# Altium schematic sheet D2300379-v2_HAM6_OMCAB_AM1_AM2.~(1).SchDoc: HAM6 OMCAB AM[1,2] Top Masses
size C; Engineer: L. Sanchez; Organization: LIGO Laboratory; Address1: California Institute of Technology; Address2: Massachusetts Institute of Technology; DocumentNumber: D2300379; Revision: v2; SheetNumber: 5; SheetTotal: 9
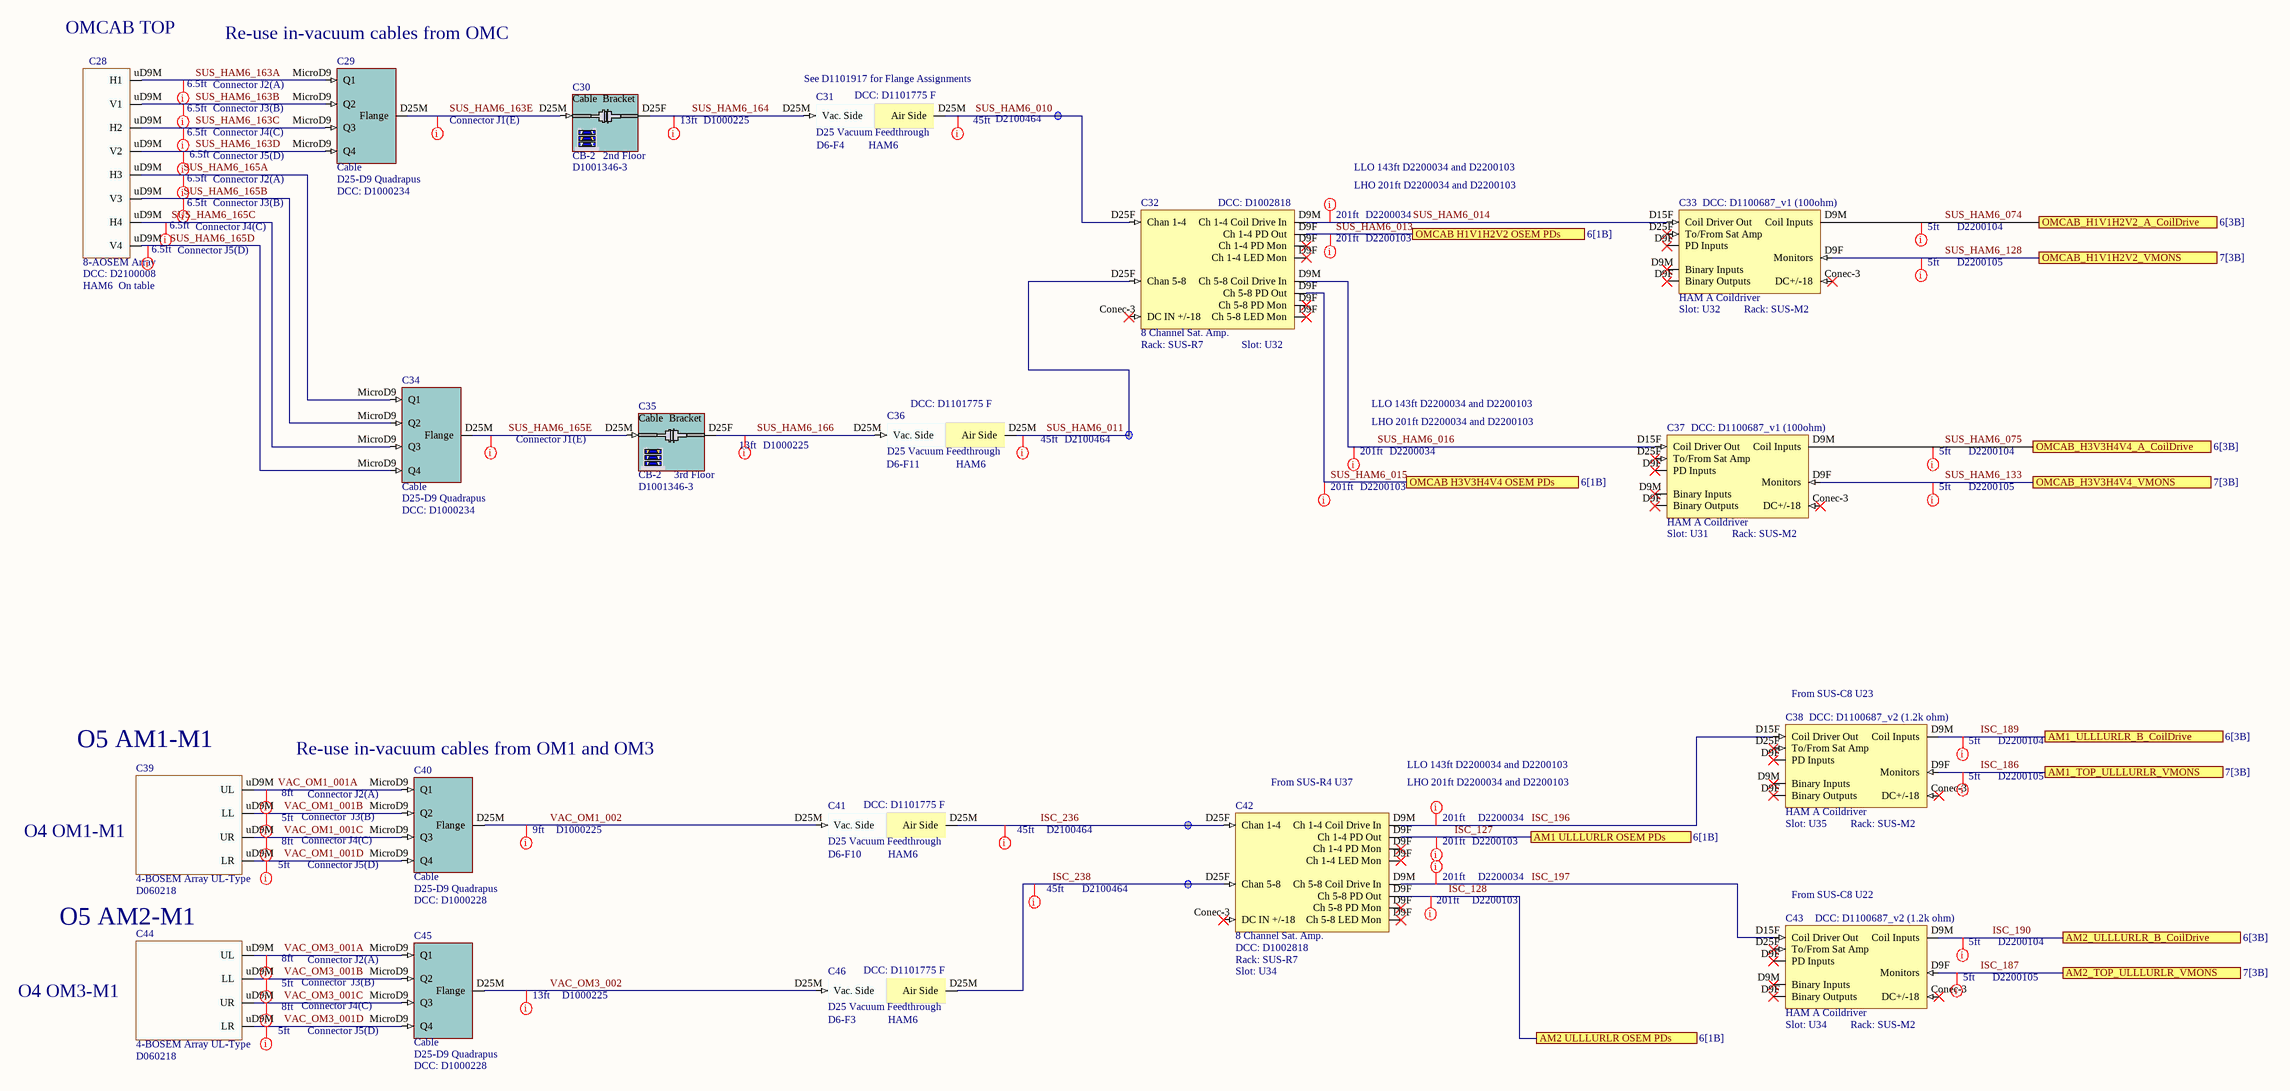
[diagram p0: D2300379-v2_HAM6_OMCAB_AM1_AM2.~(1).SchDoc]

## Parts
C28  8-AOSEM Array  DCC: D2100008  Rack: HAM6  Slot: On table
C29  Cable  value D25-D9 Quadrapus  DCC: D1000234
C30  Rack: CB-2  DCC: D1001346-3  Slot: 2nd Floor  (hidden comment: D1001346-3 2nd Cable Bracket)
C31  D25 Vacuum Feedthrough  DCC: D1101775 F  Feedthrough: D6-F4  Chamber: HAM6
C32  8 Channel Sat. Amp.  DCC: D1002818  Rack: SUS-R7  Slot: U32
C33  HAM A Coildriver  DCC: D1100687_v1 (100ohm)  Rack: SUS-M2  Slot: U32
C34  Cable  value D25-D9 Quadrapus  DCC: D1000234
C35  Rack: CB-2  DCC: D1001346-3  Slot: 3rd Floor  (hidden comment: D1001346-3 3rd Cable Bracket)
C36  D25 Vacuum Feedthrough  DCC: D1101775 F  Feedthrough: D6-F11  Chamber: HAM6
C37  HAM A Coildriver  DCC: D1100687_v1 (100ohm)  Rack: SUS-M2  Slot: U31
C38  HAM A Coildriver  DCC: D1100687_v2 (1.2k ohm)  Rack: SUS-M2  Slot: U35
C39  4-BOSEM Array UL-Type  DCC: D060218
C40  Cable  value D25-D9 Quadrapus  DCC: D1000228
C41  D25 Vacuum Feedthrough  DCC: D1101775 F  Feedthrough: D6-F10  Chamber: HAM6
C42  8 Channel Sat. Amp.  DCC: D1002818  Rack: SUS-R7  Slot: U34
C43  HAM A Coildriver  DCC: D1100687_v2 (1.2k ohm)  Rack: SUS-M2  Slot: U34
C44  4-BOSEM Array UL-Type  DCC: D060218
C45  Cable  value D25-D9 Quadrapus  DCC: D1000228
C46  D25 Vacuum Feedthrough  DCC: D1101775 F  Feedthrough: D6-F3  Chamber: HAM6

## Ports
AM1 ULLLURLR OSEM PDs (see 6[1B]), AM1_TOP_ULLLURLR_VMONS (see 7[3B]), AM1_ULLLURLR_B_CoilDrive (see 6[3B]), AM2 ULLLURLR OSEM PDs (see 6[1B]), AM2_TOP_ULLLURLR_VMONS (see 7[3B]), AM2_ULLLURLR_B_CoilDrive (see 6[3B]), OMCAB H1V1H2V2 OSEM PDs (see 6[1B]), OMCAB H3V3H4V4 OSEM PDs (see 6[1B]), OMCAB_H1V1H2V2_A_CoilDrive (see 6[3B]), OMCAB_H1V1H2V2_VMONS (see 7[3B]), OMCAB_H3V3H4V4_A_CoilDrive (see 6[3B]), OMCAB_H3V3H4V4_VMONS (see 7[3B])

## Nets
ISC_127: C42.D9F(Ch_1-4_PD_Out) ; port AM1 ULLLURLR OSEM PDs
ISC_128: C42.D9F(Ch_5-8_PD_Out) ; port AM2 ULLLURLR OSEM PDs
ISC_186: C38.D9F(PD_Inputs) ; port AM1_TOP_ULLLURLR_VMONS
ISC_187: C43.D9F(PD_Inputs) ; port AM2_TOP_ULLLURLR_VMONS
ISC_189: C38.D9M(Coil_Inputs) ; port AM1_ULLLURLR_B_CoilDrive
ISC_190: C43.D9M(Coil_Inputs) ; port AM2_ULLLURLR_B_CoilDrive
ISC_196: C38.D15F(Coil_Driver_Out) C42.D9M(Ch_1-4_Coil_Drive_In)
ISC_197: C42.D9M(Ch_5-8_Coil_Drive_In) C43.D15F(Coil_Driver_Out)
ISC_236: C41.D25M(Air_Side) C42.D25F(Chan_1-4)
ISC_238: C42.D25F(Chan_5-8) C46.D25M(Air_Side)
SUS_HAM6_010: C31.D25M(Air_Side) C32.D25F(Chan_1-4)
SUS_HAM6_011: C32.D25F(Chan_5-8) C36.D25M(Air_Side)
SUS_HAM6_013: C32.D9F(Ch_1-4_PD_Out) ; port OMCAB H1V1H2V2 OSEM PDs
SUS_HAM6_014: C32.D9M(Ch_1-4_Coil_Drive_In) C33.D15F(Coil_Driver_Out)
SUS_HAM6_015: C32.D9F(Ch_5-8_PD_Out) ; port OMCAB H3V3H4V4 OSEM PDs
SUS_HAM6_016: C32.D9M(Ch_5-8_Coil_Drive_In) C37.D15F(Coil_Driver_Out)
SUS_HAM6_074: C33.D9M(Coil_Inputs) ; port OMCAB_H1V1H2V2_A_CoilDrive
SUS_HAM6_075: C37.D9M(Coil_Inputs) ; port OMCAB_H3V3H4V4_A_CoilDrive
SUS_HAM6_128: C33.D9F(PD_Inputs) ; port OMCAB_H1V1H2V2_VMONS
SUS_HAM6_133: C37.D9F(PD_Inputs) ; port OMCAB_H3V3H4V4_VMONS
SUS_HAM6_163A: C28.uD9M(H1) C29.MicroD9(Q1)
SUS_HAM6_163B: C28.uD9M(V1) C29.MicroD9(Q2)
SUS_HAM6_163C: C28.uD9M(H2) C29.MicroD9(Q3)
SUS_HAM6_163D: C28.uD9M(V2) C29.MicroD9(Q4)
SUS_HAM6_163E: C29.D25M(Flange) C30.D25M
SUS_HAM6_164: C30.D25F C31.D25M(Vac._Side)
SUS_HAM6_165A: C28.uD9M(H3) C34.MicroD9(Q1)
SUS_HAM6_165B: C28.uD9M(V3) C34.MicroD9(Q2)
SUS_HAM6_165C: C28.uD9M(H4) C34.MicroD9(Q3)
SUS_HAM6_165D: C28.uD9M(V4) C34.MicroD9(Q4)
SUS_HAM6_165E: C34.D25M(Flange) C35.D25M
SUS_HAM6_166: C35.D25F C36.D25M(Vac._Side)
VAC_OM1_001A: C39.uD9M(UL) C40.MicroD9(Q1)
VAC_OM1_001B: C39.uD9M(LL) C40.MicroD9(Q2)
VAC_OM1_001C: C39.uD9M(UR) C40.MicroD9(Q3)
VAC_OM1_001D: C39.uD9M(LR) C40.MicroD9(Q4)
VAC_OM1_002: C40.D25M(Flange) C41.D25M(Vac._Side)
VAC_OM3_001A: C44.uD9M(UL) C45.MicroD9(Q1)
VAC_OM3_001B: C44.uD9M(LL) C45.MicroD9(Q2)
VAC_OM3_001C: C44.uD9M(UR) C45.MicroD9(Q3)
VAC_OM3_001D: C44.uD9M(LR) C45.MicroD9(Q4)
VAC_OM3_002: C45.D25M(Flange) C46.D25M(Vac._Side)

Not connected (* = marked no-connect by the designer): C32 Conec-3(DC_IN_+/-18)*; C33 Conec-3(DC+/-18)* D25F(To/From_Sat_Amp)*; C37 Conec-3(DC+/-18)* D25F(To/From_Sat_Amp)*; C38 Conec-3(DC+/-18)* D25F(To/From_Sat_Amp)*; C42 Conec-3(DC_IN_+/-18)*; C43 Conec-3(DC+/-18)* D25F(To/From_Sat_Amp)*

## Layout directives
Length: 6.5ft; DCC: Connector J1(E): SUS_HAM6_163E, SUS_HAM6_165E
Length: 45ft; DCC: D2100464: ISC_236, ISC_238, SUS_HAM6_010, SUS_HAM6_011
Length: 6.5ft; DCC: Connector J2(A): SUS_HAM6_163A, SUS_HAM6_165A
Length: 6.5ft; DCC: Connector J3(B): SUS_HAM6_163B, SUS_HAM6_165B
Length: 13ft; DCC: D1000225: SUS_HAM6_164, SUS_HAM6_166, VAC_OM3_002
Length: 6.5ft; DCC: Connector J4(C): SUS_HAM6_163C, SUS_HAM6_165C
Length: 6.5ft; DCC: Connector J5(D): SUS_HAM6_163D, SUS_HAM6_165D
Length: 5ft; DCC: D2200105: ISC_186, ISC_187, SUS_HAM6_128, SUS_HAM6_133
Length: 5ft; DCC: D2200104: ISC_189, ISC_190, SUS_HAM6_074, SUS_HAM6_075
Length: 201ft; DCC: D2200034: ISC_196, ISC_197, SUS_HAM6_014, SUS_HAM6_016
Length: 201ft; DCC: D2200103: ISC_127, ISC_128, SUS_HAM6_013, SUS_HAM6_015
Length: 9ft; DCC: D1000225: VAC_OM1_002
Length: 8ft; DCC: Connector J2(A): VAC_OM1_001A, VAC_OM3_001A
Length: 5ft; DCC: Connector  J3(B): VAC_OM1_001B, VAC_OM3_001B
Length: 8ft; DCC: Connector J4(C): VAC_OM1_001C, VAC_OM3_001C
Length: 5ft; DCC: Connector J5(D): VAC_OM1_001D, VAC_OM3_001D

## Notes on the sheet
- (near C28) OMCAB TOP
- (near C29) Re-use in-vacuum cables from OMC
- (near C31) See D1101917 for Flange Assignments
- LLO 143ft D2200034 and D2200103
- LHO 201ft D2200034 and D2200103
- O5 AM1-M1
- (near C40) Re-use in-vacuum cables from OM1 and OM3
- (near C38) From SUS-C8 U23
- (near C42) From SUS-R4 U37
- (near C42) LHO 201ft D2200034 and D2200103
- O4 OM1-M1
- O5 AM2-M1
- (near C43) From SUS-C8 U22
- O4 OM3-M1

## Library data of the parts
C28 = AOSEM_BHSS_M1: BHSS Suspended Platform AOSEM Array
C29 C34 C40 C45 = Flange: Rack: SUS-R?; Serial: Sxxxxxxx; Slot: U?; System: SUS
C30 = D1001346-3 2nd Cable Bracket: D1001346-3 2nd Cable Bracket  for HAM Tables; Serial: Sxxxxxxx; System: SUS
C31 C36 C41 C46 = VacFeedD25: Serial: Sxxxxxxx; System: ISC; Rack: R?; Slot: U?
C32 C42 = 8 Channel Sat. Amp.: Serial: Sxxxxxxx; System: ISC
C33 C37 C38 C43 = HAM A Coildriver: Serial: Sxxxxxxx; System: ISC
C35 = D1001346-3 3rd Cable Bracket: D1001346-3 3rd Cable Bracket for HAM Tables; Serial: Sxxxxxxx; System: SUS
C39 C44 = 4-BOSEM Array UL-Type: Rack: R?; Slot: U?; Serial: Sxxxxxxx; System: SUS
